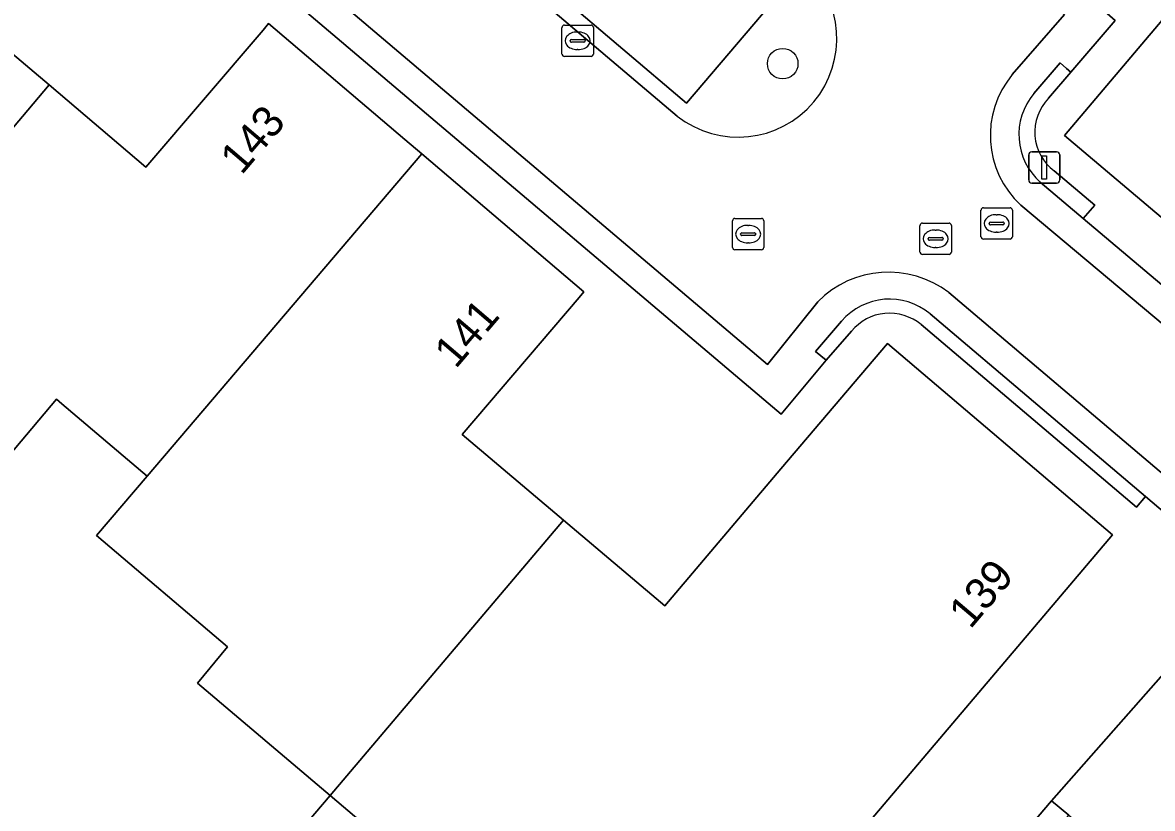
# Model space of a CAD drawing. Extents: x 156412 to 157779, y 382335 to 383768.
# Drawn here: x 156999.08 to 157035.16, y 382585.67 to 382610.78 of the extents above; entities that cross this region are included whole.
import ezdxf

# ---------------------------------------------------------------- set-up
doc = ezdxf.new("R2010")
doc.units = 0
for name, color, linetype in [('IMGEO_Berm_groen', 7, 'Continuous'), ('IMGEO_Boom', 7, 'Continuous'), ('IMGEO_Erf', 7, 'Continuous'), ('IMGEO_Groenvoorziening', 7, 'Continuous'), ('IMGEO_Haag', 7, 'Continuous'), ('IMGEO_Kolk', 7, 'Continuous'), ('IMGEO_Lichtmast', 7, 'Continuous'), ('IMGEO_Pand', 7, 'Continuous'), ('IMGEO_Pand_nummerreeks', 7, 'Continuous'), ('IMGEO_Parkeervlak_open', 7, 'Continuous'), ('IMGEO_Rijbaan_lokaal_open', 7, 'Continuous'), ('IMGEO_Rioolput', 7, 'Continuous'), ('IMGEO_Voetpad_open', 7, 'Continuous')]:
    doc.layers.add(name, color=color, linetype=linetype)

msp = doc.modelspace()

# ---------------------------------------------------------------- linework, layer by layer
at = {"layer": 'IMGEO_Berm_groen'}
msp.add_lwpolyline([(157024.026, 382612.615), (157020.282, 382608.203), (157012.15, 382615.113), (157015.907, 382619.51), (157004.294, 382629.355), (157003.942, 382628.943), (157006.64, 382626.676), (157003.26, 382622.691), (157001.992, 382623.762), (157001.632, 382623.366), (157003.318, 382621.96), (157007.047, 382626.356), (157015.173, 382619.444), (157011.426, 382615.051), (157019.984, 382607.789)], dxfattribs=at)
msp.add_arc((157021.929, 382610.266), 3.149, 231.864, 48.2405, dxfattribs=at)
at = {"layer": 'IMGEO_Boom'}
msp.add_circle((157023.351, 382609.467), 0.489, dxfattribs=at)
at = {"layer": 'IMGEO_Erf'}
for points in [[(157032.018, 382606.037), (157033.314, 382604.947), (157032.946, 382604.52), (157041.703, 382597.123), (157047.972, 382604.539), (157048.196, 382604.798), (157060.586, 382619.348), (157029.826, 382645.416), (156987.205, 382681.476), (156986.214, 382682.315), (156984.143, 382684.067), (156942.915, 382635.543), (156901.626, 382586.899), (156977.949, 382522.266), (156980.608, 382525.348), (156995.995, 382543.705), (156987.057, 382551.292)], [(157025.547, 382600.915), (157024.742, 382599.993), (157023.299, 382598.267), (156996.744, 382620.777), (156970.587, 382642.986), (156981.231, 382655.569), (157028.044, 382615.928), (157032.619, 382612.041), (157033.972, 382610.85), (157032.555, 382609.191), (157031.842, 382608.361)], [(157052.541, 382616.375), (157039.552, 382601.073), (157032.351, 382607.17), (157035.583, 382610.995)], [(156996.558, 382611.649), (156999.924, 382608.789), (157003.02, 382606.157), (157006.762, 382610.541), (157006.937, 382610.746), (157011.288, 382607.044), (157011.825, 382606.587), (157017.006, 382602.178), (157016.849, 382601.995), (157013.114, 382597.618), (157016.349, 382594.878), (157019.584, 382592.138), (157023.297, 382596.515), (157026.698, 382600.527), (157033.881, 382594.404), (157021.609, 382579.925)], [(157031.936, 382585.906), (157038.117, 382592.933), (157034.938, 382595.632), (157034.651, 382595.29), (157027.77, 382601.127)], [(157005.734, 382582.345), (157008.899, 382586.082), (157004.665, 382589.671), (157005.625, 382590.826), (157001.443, 382594.392), (157003.061, 382596.286), (157000.331, 382598.599), (157000.161, 382598.747), (156998.232, 382596.46)], [(156990.803, 382555.536), (156999.66, 382548.012), (157006.94, 382556.508), (157019.133, 382570.849), (157031.936, 382585.906)]]:
    msp.add_lwpolyline(points, dxfattribs=at)
for centre, radius, start, end in [((157032.959, 382607.277), 1.557, 135.863, 232.7987), ((157026.764, 382599.92), 1.572, 50.1791, 140.7161)]:
    msp.add_arc(centre, radius, start, end, dxfattribs=at)
at = {"layer": 'IMGEO_Groenvoorziening'}
for points in [[(157031.842, 382608.361), (157032.555, 382609.191), (157032.419, 382609.31), (157032.211, 382609.492), (157031.375, 382608.517)], [(157031.577, 382605.677), (157032.946, 382604.52), (157033.314, 382604.947), (157032.018, 382606.037)], [(157025.23, 382601.237), (157024.4, 382600.265), (157024.742, 382599.993), (157025.547, 382600.915)], [(157027.77, 382601.127), (157034.651, 382595.29), (157034.938, 382595.632), (157028.061, 382601.47)]]:
    msp.add_lwpolyline(points, dxfattribs=at)
for points in [[(157041.035, 382590.456), (157038.117, 382592.933), (157031.936, 382585.906), (157032.49, 382585.447), (157034.725, 382583.574), (157034.993, 382583.337)], [(157032.49, 382585.447), (157031.936, 382585.906), (157019.133, 382570.849), (157006.94, 382556.508), (156999.66, 382548.012), (157000.311, 382547.459), (157000.556, 382547.732)]]:
    msp.add_lwpolyline(points, close=True, dxfattribs=at)
for centre, radius, start, end in [((157032.929, 382607.2), 2.036, 139.717, 228.4199), ((157032.959, 382607.277), 1.557, 135.863, 232.7987), ((157026.763, 382599.922), 2.02, 50.0209, 139.3892), ((157026.764, 382599.92), 1.572, 50.1791, 140.7161)]:
    msp.add_arc(centre, radius, start, end, dxfattribs=at)
at = {"layer": 'IMGEO_Haag'}
for points in [[(157032.555, 382609.191), (157032.419, 382609.31), (157032.211, 382609.492), (157031.375, 382608.517)], [(157031.842, 382608.361), (157032.555, 382609.191)], [(157031.577, 382605.677), (157032.946, 382604.52), (157033.314, 382604.947), (157032.018, 382606.037)], [(157025.23, 382601.237), (157024.4, 382600.265), (157024.742, 382599.993), (157025.547, 382600.915)], [(157027.77, 382601.127), (157034.651, 382595.29), (157034.938, 382595.632), (157028.061, 382601.47)]]:
    msp.add_lwpolyline(points, dxfattribs=at)
for points in [[(157041.035, 382590.456), (157038.117, 382592.933), (157031.936, 382585.906), (157032.49, 382585.447), (157034.725, 382583.574), (157034.993, 382583.337)], [(157032.49, 382585.447), (157031.936, 382585.906), (157019.133, 382570.849), (157006.94, 382556.508), (156999.66, 382548.012), (157000.311, 382547.459), (157000.556, 382547.732)]]:
    msp.add_lwpolyline(points, close=True, dxfattribs=at)
for centre, radius, start, end in [((157032.929, 382607.2), 2.036, 139.717, 228.4199), ((157032.959, 382607.277), 1.557, 135.863, 232.7987), ((157026.763, 382599.922), 2.02, 50.0209, 139.3892), ((157026.764, 382599.92), 1.572, 50.1791, 140.7161)]:
    msp.add_arc(centre, radius, start, end, dxfattribs=at)
at = {"layer": 'IMGEO_Kolk'}
for p, q in [((157016.304, 382609.773), (157016.304, 382610.625)), ((157016.379, 382610.699), (157017.231, 382610.699)), ((157017.305, 382610.625), (157017.305, 382609.773)), ((157016.563, 382610.193), (157016.563, 382610.205)), ((157017.001, 382610.156), (157016.603, 382610.156)), ((157016.606, 382610.242), (157017.004, 382610.242)), ((157016.792, 382610.479), (157016.817, 382610.479)), ((157017.047, 382610.205), (157017.047, 382610.193)), ((157016.815, 382609.919), (157016.79, 382609.919)), ((157017.231, 382609.699), (157016.379, 382609.699))]:
    msp.add_line(p, q, dxfattribs=at)
for points in [[(157016.304, 382609.773), (157016.304, 382610.625)], [(157016.379, 382610.699), (157017.231, 382610.699)], [(157017.305, 382610.625), (157017.305, 382609.773)], [(157017.231, 382609.699), (157016.379, 382609.699)]]:
    msp.add_lwpolyline(points, dxfattribs=at)
for centre, radius, start, end in [((157016.381, 382610.623), 0.0765, 91.552, 178.448), ((157016.381, 382610.623), 0.0765, 91.552, 178.448), ((157017.229, 382610.623), 0.0765, 1.552, 88.448), ((157017.229, 382610.623), 0.0765, 1.552, 88.448), ((157016.603, 382610.202), 0.0403, 85.8775, 175.7526), ((157016.6, 382610.192), 0.0366, 178.938, 274.7102), ((157017.004, 382610.199), 0.043, 264.8664, 352.4533), ((157017.008, 382610.204), 0.0386, 1.7309, 96.639), ((157016.381, 382609.775), 0.0765, 181.552, 268.448), ((157016.381, 382609.775), 0.0765, 181.552, 268.448), ((157017.229, 382609.775), 0.0765, 271.552, 358.448), ((157017.229, 382609.775), 0.0765, 271.552, 358.448)]:
    msp.add_arc(centre, radius, start, end, dxfattribs=at)
for centre, major_axis, ratio, start_param, end_param in [((157016.791, 382610.199), (-0.387, 0.002), 0.722429, 4.712389, 7.853982), ((157016.816, 382610.199), (-0.39, 0.002), 0.717154, 1.570796, 4.712389)]:
    msp.add_ellipse(centre, major_axis=major_axis, ratio=ratio, start_param=start_param, end_param=end_param, dxfattribs=at)
at = {"layer": 'IMGEO_Lichtmast'}
for p, q in [((157031.208, 382605.75), (157031.208, 382606.55)), ((157031.208, 382606.55), (157031.208, 382605.75)), ((157031.308, 382606.65), (157032.098, 382606.65)), ((157032.098, 382606.65), (157031.308, 382606.65)), ((157032.198, 382606.55), (157032.198, 382605.75)), ((157032.198, 382605.75), (157032.198, 382606.55)), ((157032.098, 382605.65), (157031.308, 382605.65)), ((157031.308, 382605.65), (157032.098, 382605.65))]:
    msp.add_line(p, q, dxfattribs=at)
msp.add_lwpolyline([(157031.628, 382606.525), (157031.778, 382606.525), (157031.778, 382605.775), (157031.628, 382605.775), (157031.628, 382606.525)], dxfattribs=at)
for centre, start, end in [((157031.308, 382606.55), 90, 180), ((157031.308, 382606.55), 90, 180), ((157032.098, 382606.55), 0, 90), ((157032.098, 382606.55), 360, 90), ((157031.308, 382605.75), 180, 270), ((157031.308, 382605.75), 180, 270), ((157032.098, 382605.75), 270, 0), ((157032.098, 382605.75), 270, 0)]:
    msp.add_arc(centre, 0.1, start, end, dxfattribs=at)
at = {"layer": 'IMGEO_Pand'}
for points in [[(157046.553, 382623.934), (157035.583, 382610.995), (157032.351, 382607.17), (157039.552, 382601.073), (157052.541, 382616.375), (157054.766, 382618.997), (157050.957, 382622.22), (157047.699, 382624.977), (157047.549, 382625.107)], [(156994.788, 382621.028), (156986.03, 382610.723), (156989.371, 382607.888), (156989.764, 382607.541), (156990.16, 382607.208), (156987.673, 382604.263), (156987.666, 382604.254), (156987.576, 382604.152), (156992.484, 382600.002), (156993.145, 382600.75), (156999.924, 382608.789), (156996.558, 382611.649), (157000.288, 382616.038), (157000.444, 382616.221), (156994.906, 382620.928)], [(157011.825, 382606.587), (157011.288, 382607.044), (157006.937, 382610.746), (157006.762, 382610.541), (157003.02, 382606.157), (156999.924, 382608.789), (156993.145, 382600.75), (156998.232, 382596.46), (157000.161, 382598.747), (157000.331, 382598.599), (157003.061, 382596.286)], [(157013.114, 382597.618), (157016.849, 382601.995), (157017.006, 382602.178), (157011.825, 382606.587), (157003.061, 382596.286), (157001.443, 382594.392), (157005.625, 382590.826), (157004.665, 382589.671), (157008.899, 382586.082), (157016.349, 382594.878)], [(157033.881, 382594.404), (157026.698, 382600.527), (157023.297, 382596.515), (157019.584, 382592.138), (157016.349, 382594.878), (157008.899, 382586.082), (157010.883, 382584.4), (157014.822, 382581.061), (157017.085, 382583.73), (157017.181, 382583.649), (157018.794, 382582.282), (157018.826, 382582.255), (157021.52, 382579.972), (157021.609, 382579.925)], [(157010.883, 382584.4), (157008.899, 382586.082), (157005.734, 382582.345), (157007.719, 382580.664)]]:
    msp.add_lwpolyline(points, close=True, dxfattribs=at)
at = {"layer": 'IMGEO_Parkeervlak_open'}
msp.add_lwpolyline([(157015.907, 382619.51), (157012.15, 382615.113), (157020.282, 382608.203), (157024.026, 382612.615), (157023.692, 382612.881)], close=True, dxfattribs=at)
at = {"layer": 'IMGEO_Rijbaan_lokaal_open'}
for points in [[(157030.684, 382609.119), (157032.355, 382611.034), (156981.406, 382654.235), (156971.863, 382643.106), (157022.87, 382599.849), (157024.469, 382601.859)], [(157019.984, 382607.789), (157011.426, 382615.051), (157003.318, 382621.96), (157001.632, 382623.366), (157000.572, 382624.262), (156989.188, 382633.906), (156981.062, 382640.794)], [(157028.653, 382602.153), (157041.599, 382591.168), (157043.996, 382594.008), (157030.951, 382604.943)]]:
    msp.add_lwpolyline(points, dxfattribs=at)
for centre, radius, start, end in [((157021.929, 382610.266), 3.149, 231.864, 48.2405), ((157033.026, 382607.172), 3.045, 140.2605, 227.0561), ((157026.728, 382599.633), 3.171, 52.6152, 135.4237)]:
    msp.add_arc(centre, radius, start, end, dxfattribs=at)
at = {"layer": 'IMGEO_Rioolput'}
for p, q in [((157029.684, 382603.935), (157029.684, 382604.787)), ((157029.759, 382604.861), (157030.611, 382604.861)), ((157030.685, 382604.787), (157030.685, 382603.935)), ((157021.748, 382603.594), (157021.748, 382604.446)), ((157021.823, 382604.52), (157022.675, 382604.52)), ((157022.749, 382604.446), (157022.749, 382603.594)), ((157027.811, 382604.371), (157028.663, 382604.371)), ((157029.943, 382604.355), (157029.943, 382604.367)), ((157029.986, 382604.404), (157030.384, 382604.404)), ((157030.172, 382604.641), (157030.197, 382604.641)), ((157030.427, 382604.367), (157030.427, 382604.355)), ((157022.007, 382604.014), (157022.007, 382604.026)), ((157022.05, 382604.063), (157022.448, 382604.063)), ((157022.236, 382604.3), (157022.261, 382604.3)), ((157022.491, 382604.026), (157022.491, 382604.014)), ((157027.736, 382603.445), (157027.736, 382604.297)), ((157028.224, 382604.151), (157028.249, 382604.151)), ((157028.737, 382604.297), (157028.737, 382603.445)), ((157030.381, 382604.318), (157029.983, 382604.318)), ((157030.195, 382604.081), (157030.17, 382604.081)), ((157022.445, 382603.977), (157022.047, 382603.977)), ((157022.259, 382603.74), (157022.234, 382603.74)), ((157027.995, 382603.865), (157027.995, 382603.877)), ((157028.433, 382603.828), (157028.035, 382603.828)), ((157028.038, 382603.914), (157028.436, 382603.914)), ((157028.479, 382603.877), (157028.479, 382603.865)), ((157030.611, 382603.861), (157029.759, 382603.861)), ((157022.675, 382603.52), (157021.823, 382603.52)), ((157028.663, 382603.371), (157027.811, 382603.371)), ((157028.247, 382603.591), (157028.222, 382603.591))]:
    msp.add_line(p, q, dxfattribs=at)
for points in [[(157029.684, 382603.935), (157029.684, 382604.787)], [(157029.759, 382604.861), (157030.611, 382604.861)], [(157030.685, 382604.787), (157030.685, 382603.935)], [(157021.748, 382603.594), (157021.748, 382604.446)], [(157021.823, 382604.52), (157022.675, 382604.52)], [(157022.749, 382604.446), (157022.749, 382603.594)], [(157027.811, 382604.371), (157028.663, 382604.371)], [(157027.736, 382603.445), (157027.736, 382604.297)], [(157028.737, 382604.297), (157028.737, 382603.445)], [(157030.611, 382603.861), (157029.759, 382603.861)], [(157022.675, 382603.52), (157021.823, 382603.52)], [(157028.663, 382603.371), (157027.811, 382603.371)]]:
    msp.add_lwpolyline(points, dxfattribs=at)
for centre, radius, start, end in [((157029.761, 382604.785), 0.0765, 91.552, 178.448), ((157029.761, 382604.785), 0.0765, 91.552, 178.448), ((157030.609, 382604.785), 0.0765, 1.552, 88.448), ((157030.609, 382604.785), 0.0765, 1.552, 88.448), ((157021.825, 382604.444), 0.0765, 91.552, 178.448), ((157021.825, 382604.444), 0.0765, 91.552, 178.448), ((157022.673, 382604.444), 0.0765, 1.552, 88.448), ((157022.673, 382604.444), 0.0765, 1.552, 88.448), ((157027.813, 382604.295), 0.0765, 91.552, 178.448), ((157027.813, 382604.295), 0.0765, 91.552, 178.448), ((157028.661, 382604.295), 0.0765, 1.552, 88.448), ((157028.661, 382604.295), 0.0765, 1.552, 88.448), ((157029.983, 382604.364), 0.0403, 85.8775, 175.7526), ((157030.388, 382604.366), 0.0386, 1.7309, 96.639), ((157022.047, 382604.023), 0.0403, 85.8775, 175.7526), ((157022.044, 382604.013), 0.0366, 178.938, 274.7102), ((157022.448, 382604.02), 0.043, 264.8664, 352.4533), ((157022.452, 382604.025), 0.0386, 1.7309, 96.639), ((157029.98, 382604.354), 0.0366, 178.938, 274.7102), ((157030.384, 382604.361), 0.043, 264.8664, 352.4533), ((157028.035, 382603.874), 0.0403, 85.8775, 175.7526), ((157028.032, 382603.864), 0.0366, 178.938, 274.7102), ((157028.436, 382603.871), 0.043, 264.8664, 352.4533), ((157028.44, 382603.876), 0.0386, 1.7309, 96.639), ((157029.761, 382603.937), 0.0765, 181.552, 268.448), ((157029.761, 382603.937), 0.0765, 181.552, 268.448), ((157030.609, 382603.937), 0.0765, 271.552, 358.448), ((157030.609, 382603.937), 0.0765, 271.552, 358.448), ((157021.825, 382603.596), 0.0765, 181.552, 268.448), ((157021.825, 382603.596), 0.0765, 181.552, 268.448), ((157022.673, 382603.596), 0.0765, 271.552, 358.448), ((157022.673, 382603.596), 0.0765, 271.552, 358.448), ((157027.813, 382603.447), 0.0765, 181.552, 268.448), ((157027.813, 382603.447), 0.0765, 181.552, 268.448), ((157028.661, 382603.447), 0.0765, 271.552, 358.448), ((157028.661, 382603.447), 0.0765, 271.552, 358.448)]:
    msp.add_arc(centre, radius, start, end, dxfattribs=at)
for centre, major_axis, ratio, start_param, end_param in [((157030.171, 382604.361), (-0.387, 0.002), 0.722429, 4.712389, 7.853982), ((157030.196, 382604.361), (-0.39, 0.002), 0.717154, 1.570796, 4.712389), ((157022.235, 382604.02), (-0.387, 0.002), 0.722429, 4.712389, 7.853982), ((157022.26, 382604.02), (-0.39, 0.002), 0.717154, 1.570796, 4.712389), ((157028.223, 382603.871), (-0.387, 0.002), 0.722429, 4.712389, 7.853982), ((157028.248, 382603.871), (-0.39, 0.002), 0.717154, 1.570796, 4.712389)]:
    msp.add_ellipse(centre, major_axis=major_axis, ratio=ratio, start_param=start_param, end_param=end_param, dxfattribs=at)
at = {"layer": 'IMGEO_Voetpad_open'}
for points in [[(157031.375, 382608.517), (157032.211, 382609.492), (157032.419, 382609.31), (157032.555, 382609.191), (157033.972, 382610.85), (157032.619, 382612.041), (157028.044, 382615.928), (156981.231, 382655.569), (156970.587, 382642.986), (156996.744, 382620.777), (157023.299, 382598.267), (157024.742, 382599.993), (157024.4, 382600.265), (157025.23, 382601.237)], [(157024.469, 382601.859), (157022.87, 382599.849), (156971.863, 382643.106), (156981.406, 382654.235)], [(156981.406, 382654.235), (157032.355, 382611.034), (157030.684, 382609.119)], [(157030.951, 382604.943), (157043.996, 382594.008), (157044.581, 382594.691), (157041.703, 382597.123), (157032.946, 382604.52), (157031.577, 382605.677)], [(157028.061, 382601.47), (157034.938, 382595.632), (157038.117, 382592.933), (157041.035, 382590.456), (157041.599, 382591.168), (157028.653, 382602.153)]]:
    msp.add_lwpolyline(points, dxfattribs=at)
for centre, radius, start, end in [((157033.026, 382607.172), 3.045, 140.2605, 227.0561), ((157032.929, 382607.2), 2.036, 139.717, 228.4199), ((157026.728, 382599.633), 3.171, 52.6152, 135.4237), ((157026.763, 382599.922), 2.02, 50.0209, 139.3892)]:
    msp.add_arc(centre, radius, start, end, dxfattribs=at)

# ---------------------------------------------------------------- texts
at = {"layer": 'IMGEO_Pand_nummerreeks'}
for s, rotation, p in [('143', 49.5136, (157006.072, 382605.882)), ('141', 49.5199, (157012.909, 382599.689)), ('139', 49.7155, (157029.342, 382591.369))]:
    msp.add_text(s, height=1, rotation=rotation, dxfattribs=at).set_placement(p)

doc.saveas('drawing.dxf')
